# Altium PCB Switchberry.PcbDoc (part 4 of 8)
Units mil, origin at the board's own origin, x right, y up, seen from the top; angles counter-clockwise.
Board outline 4500 x 3824.8 mil, 6 copper layers (L01-TOP, L02-GND, L03-SIG, L04-SIG, L05-GND, L06-BOT), stack 49.214 mil thick; 431 components, 322 nets, 1699 pads, 1274 vias.
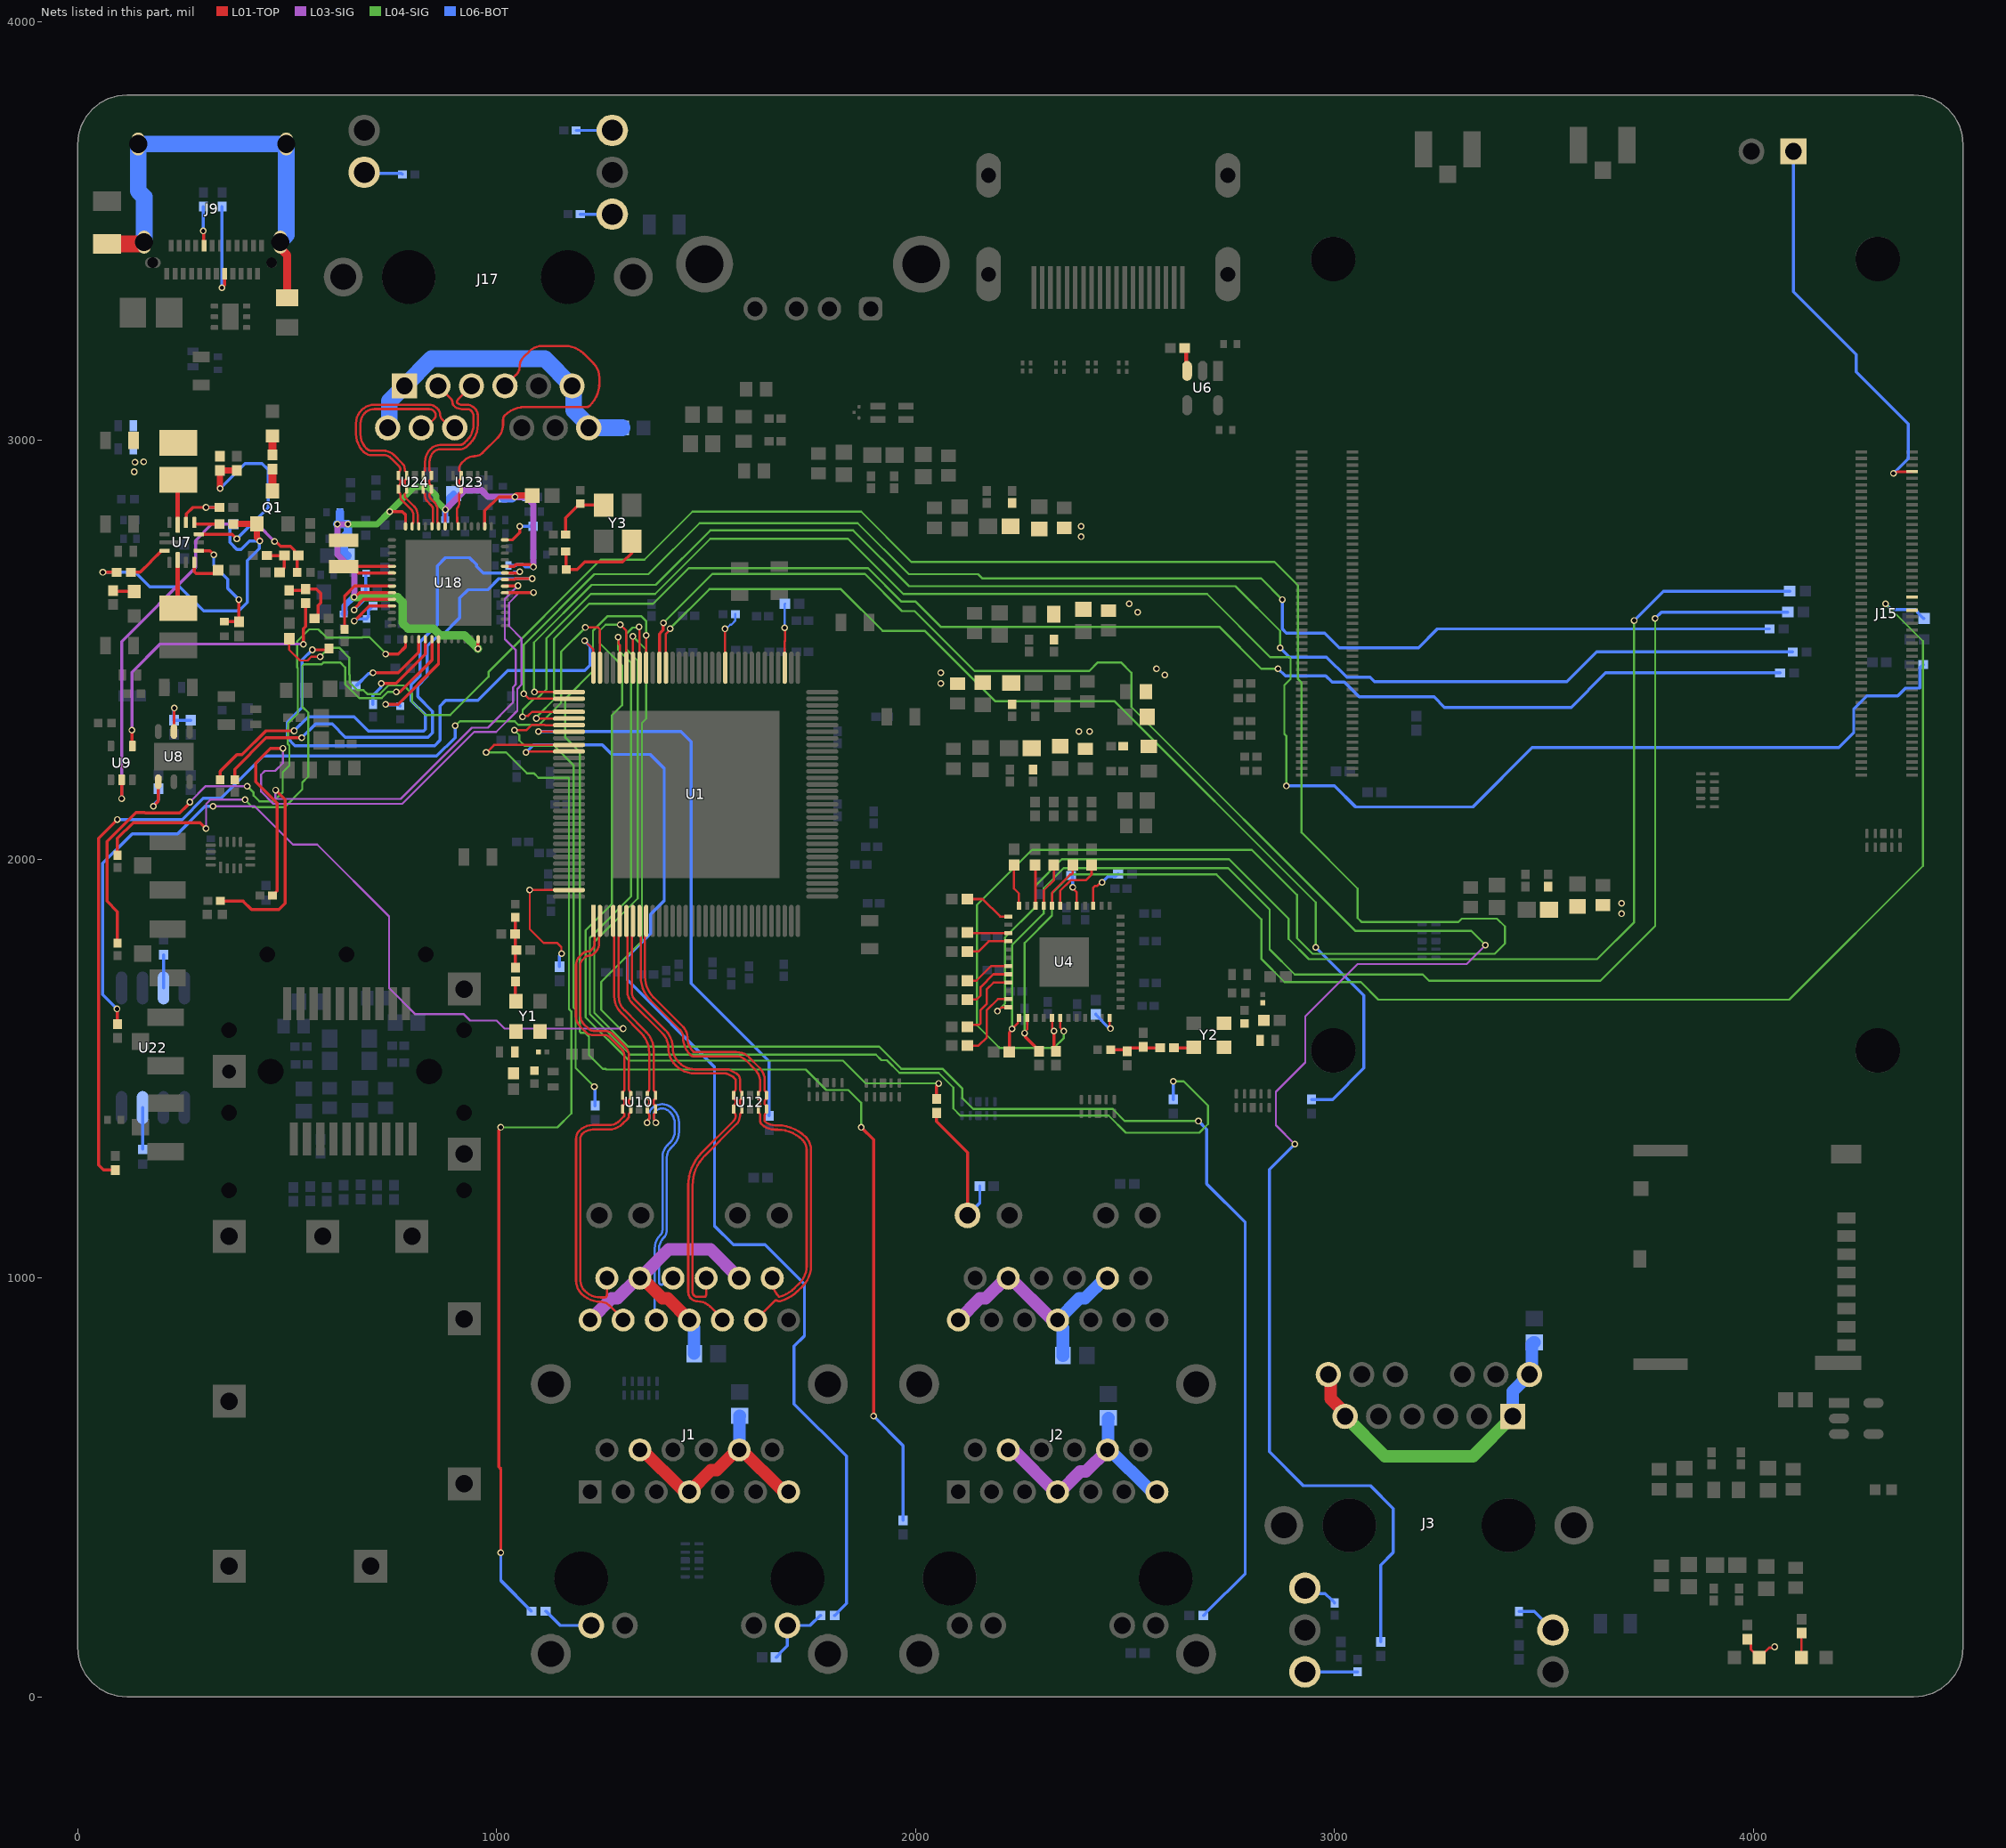
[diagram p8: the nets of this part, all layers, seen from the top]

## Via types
v1: diameter 16, hole 10, L01-TOP to L06-BOT, tented both sides, 1262 vias
v2: diameter 11.81, hole 7.87, L01-TOP to L06-BOT, tented both sides, 4 vias
v3: diameter 19.68, hole 7.87, L01-TOP to L06-BOT, tented both sides, 4 vias
v4: diameter 157.48, hole 110.24, L01-TOP to L06-BOT, tented both sides, 4 vias

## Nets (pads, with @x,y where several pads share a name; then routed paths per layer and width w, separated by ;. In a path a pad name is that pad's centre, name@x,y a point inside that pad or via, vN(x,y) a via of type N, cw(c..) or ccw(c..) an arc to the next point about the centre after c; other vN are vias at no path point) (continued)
MDI_B_P: J17.4 U18.48 U23.2 U23.9 | length 922.7
  L01-TOP w5.38: U18.48@908.62,2794.84 908.62,2799.53 ccw(c904.04,2799.53) 907.28,2802.77 cw(c910.52,2806.01) 905.94,2806.01 905.94,2816.09 ccw(c903.59,2816.09) 905.25,2817.75 905.25,2837.45 ccw(c892.18,2850.52) 910.66,2850.52 910.66,2868.5 cw(c919.05,2868.5) 913.12,2874.44 913.81,2875.13 914.07,2875.13 914.69,2875.75 ccw(c913.18,2877.26) 915.31,2877.26 U23.2@915.31,2883.56 915.31,2889.87 ccw(c913.18,2889.87) 914.69,2891.37 914.07,2892 913.81,2892 cw(c921.42,2899.6) 910.66,2899.6 910.66,2902.63 cw(c916.04,2902.63) 912.24,2906.43 913.81,2908 914.07,2908 ccw(c911.05,2911.02) 915.31,2911.02 915.31,2921.86 ccw(c911.05,2921.86) 914.07,2924.87 913.81,2924.87 912.24,2926.45 cw(c916.04,2930.25) 910.66,2930.25 910.66,2932.54 cw(c928.18,2932.54) 915.79,2944.93 923.43,2952.57 cw(c946.7,2929.31) 946.7,2962.21 ccw(c946.7,2990.59) 966.77,2970.52 1002.09,3005.85 ccw(c970.01,3037.92) 1015.38,3037.92 1015.38,3048.84 cw(c1031.16,3048.84) 1020,3060 cw(c1067.37,3012.63) 1067.37,3079.62 1215,3079.62 ccw(c1215,3090) 1222.34,3082.66 ccw(c1166.72,3138.28) 1245.38,3138.28 1245.38,3150 ccw(c1198.79,3150) 1231.73,3182.95 1207.34,3207.34 ccw(c1163.79,3163.79) 1163.79,3225.38 1109.14,3225.38 ccw(c1109.14,3180.86) 1077.66,3212.34 1065.06,3199.73 ccw(c1089.79,3175) 1054.81,3175 cw(c1030.21,3175) 1047.61,3157.61 J17.4@1020,3130
MDI_C_N: J17.2 U18.52 U24.4 U24.7 | length 481.8
  L01-TOP w5.38: U24.7@824.68,2911.02 U24.7@824.68,2916.44 ; U24.7@824.72,2909.47 824.72,2921.95 cw(c828.85,2921.95) 825.93,2924.87 826.19,2924.87 827.76,2926.45 ccw(c823.96,2930.25) 829.34,2930.25 829.34,2948.32 cw(c873.47,2948.32) 842.26,2979.52 cw(c865.08,2956.7) 865.08,2988.98 911,2988.98 ccw(c911,3006.42) 923.33,2994.09 929.61,3000.36 ccw(c893.05,3036.91) 944.75,3036.91 944.75,3058.54 ccw(c928.54,3058.54) 940,3070 ccw(c928.84,3058.84) 928.84,3074.62 917.26,3074.62 cw(c917.26,3102.07) 897.85,3082.66 cw(c905.19,3090) 894.81,3090 ccw(c882.28,3090) 891.14,3098.86 J17.2@860,3130 ; U24.7@825.93,2908 826.19,2908 827.76,2906.43 cw(c823.96,2902.63) 829.34,2902.63 829.34,2899.6 cw(c818.58,2899.6) 826.19,2892 825.93,2892 825.31,2891.37 ccw(c826.82,2889.87) 824.68,2889.87 U24.4@824.68,2883.56 824.68,2878.14 ccw(c828.95,2878.14) 825.93,2875.13 826.19,2875.13 827.76,2873.55 cw(c823.96,2869.75) 829.34,2869.75 829.34,2865.86 ccw(c844.1,2865.86) 833.66,2855.42 843.48,2845.6 cw(c831.81,2833.93) 848.32,2833.93 848.32,2806.01 cw(c843.73,2806.01) 846.97,2802.77 ccw(c850.21,2799.53) 845.63,2799.53 U18.52@845.63,2794.84
MDI_C_P: J17.3 U18.51 U24.5 U24.6 | length 478
  L01-TOP w5.38: U18.51@861.38,2794.84 861.38,2799.53 ccw(c856.79,2799.53) 860.04,2802.77 cw(c863.28,2806.01) 858.69,2806.01 858.69,2833.93 ccw(c831.81,2833.93) 850.82,2852.94 842.52,2861.24 cw(c849.29,2868.01) 839.72,2868.01 839.72,2869.75 cw(c845.09,2869.75) 841.29,2873.55 842.87,2875.13 843.12,2875.13 ccw(c840.11,2878.14) 844.37,2878.14 U24.5@844.37,2883.56 844.37,2889.87 ccw(c842.24,2889.87) 843.75,2891.37 843.12,2892 842.87,2892 cw(c850.47,2899.6) 839.72,2899.6 839.72,2902.63 cw(c845.09,2902.63) 841.29,2906.43 842.87,2908 843.12,2908 ccw(c840.11,2911.02) 844.37,2911.02 U24.6@844.37,2916.44 844.37,2921.86 ccw(c840.11,2921.86) 843.12,2924.87 842.87,2924.87 841.29,2926.45 cw(c845.09,2930.25) 839.72,2930.25 839.72,2948.32 cw(c873.47,2948.32) 849.6,2972.19 cw(c865.08,2956.7) 865.08,2978.6 911,2978.6 ccw(c911,3006.42) 930.67,2986.75 936.94,2993.02 ccw(c893.05,3036.91) 955.13,3036.91 955.13,3058.54 ccw(c928.54,3058.54) 947.34,3077.34 ccw(c928.84,3058.84) 928.84,3085 917.26,3085 cw(c917.26,3102.07) 905.19,3090 cw(c917.72,3090) 908.86,3098.86 J17.3@940,3130
MDI_D_N: J17.9 U18.55 U24.1 U24.10 | length 620.9
  L01-TOP w5.38: U18.55@798.39,2794.84 798.39,2799.53 cw(c802.97,2799.53) 799.73,2802.77 ccw(c796.49,2806.01) 801.07,2806.01 801.07,2822.76 ccw(c784.01,2822.76) 796.08,2834.82 774.3,2856.59 cw(c784.01,2866.29) 770.28,2866.29 770.28,2869.75 ccw(c764.91,2869.75) 768.71,2873.55 767.13,2875.13 766.88,2875.13 cw(c769.89,2878.14) 765.63,2878.14 U24.1@765.63,2883.56 765.63,2889.87 cw(c767.76,2889.87) 766.25,2891.37 766.88,2892 767.13,2892 ccw(c759.53,2899.6) 770.28,2899.6 770.28,2902.63 ccw(c764.91,2902.63) 768.71,2906.43 767.13,2908 766.88,2908 cw(c769.89,2911.02) 765.63,2911.02 U24.10@765.63,2916.44 765.63,2922.74 cw(c767.76,2922.74) 766.25,2924.25 766.88,2924.87 767.13,2924.87 767.83,2925.56 ccw(c761.89,2931.5) 770.28,2931.5 ccw(c761.96,2931.5) 767.85,2937.38 747.46,2957.77 ccw(c730,2940.31) 730,2965 701.16,2965 cw(c701.16,2991.16) 682.66,2972.66 681.8,2973.52 cw(c723.28,3015) 664.62,3015 664.62,3040.86 cw(c709.14,3040.86) 677.66,3072.34 cw(c708.69,3041.31) 708.69,3085.19 838.38,3085.19 cw(c838.38,3058.38) 857.34,3077.34 860.13,3074.55 cw(c847.9,3062.33) 865.19,3062.33 ccw(c882.48,3062.33) 870.25,3050.1 883.54,3036.82 ccw(c900,3053.28) J17.9@900,3030
MDI_D_P: J17.8 U18.54 U24.2 U24.9 | length 588.1
  L01-TOP w5.38: U18.54@814.13,2794.84 814.13,2799.53 ccw(c809.55,2799.53) 812.79,2802.77 cw(c816.03,2806.01) 811.45,2806.01 811.45,2822.76 ccw(c784.01,2822.76) 803.41,2842.16 783.16,2862.41 cw(c789.2,2868.44) 780.66,2868.44 780.66,2869.75 cw(c786.04,2869.75) 782.24,2873.55 783.81,2875.13 784.07,2875.13 ccw(c781.05,2878.14) 785.31,2878.14 U24.2@785.31,2883.56 785.31,2889.87 ccw(c783.18,2889.87) 784.69,2891.37 784.07,2892 783.81,2892 cw(c791.42,2899.6) 780.66,2899.6 780.66,2902.63 cw(c786.04,2902.63) 782.24,2906.43 783.81,2908 784.07,2908 ccw(c781.05,2911.02) 785.31,2911.02 U24.9@785.31,2916.44 785.31,2922.74 ccw(c783.18,2922.74) 784.69,2924.25 784.07,2924.87 783.81,2924.87 783.12,2925.56 cw(c789.05,2931.5) 780.66,2931.5 ccw(c761.96,2931.5) 775.18,2944.72 754.8,2965.11 ccw(c730,2940.31) 730,2975.38 701.16,2975.38 cw(c701.16,2991.16) 690,2980 689.14,2980.86 cw(c723.28,3015) 675,3015 675,3040.86 cw(c709.14,3040.86) 685,3065 cw(c708.69,3041.31) 708.69,3074.81 838.38,3074.81 cw(c838.38,3058.38) 850,3070 851.27,3068.73 cw(c842.71,3060.18) 854.81,3060.18 cw(c842.71,3060.18) 851.27,3051.62 836.46,3036.82 cw(c820,3053.28) J17.8@820,3030
NetC17_1: C17.1 C18.1 C19.1 L1.2 Y1.1 Y1.4
NetC23_1: C23.1 C24.1 C25.1 L2.2 Y2.1 Y2.4
NetC26_2: C26.2 J1.4 J1.7 J1.9 J1.12 | length 561.1
  L01-TOP w30: J1.9@1342,590 1347.95,590 1443.23,494.72 1455.28,494.72 J1.4@1460,490 1511.67,541.67 1525.02,541.67 1573.35,590 J1.12@1579,590 1584.95,590 1680.23,494.72 1692.28,494.72 J1.7@1697,490
  L06-BOT w30: J1.12@1579,590 1579.5,590.5 1579.5,670.96 C26.2@1580,671.46
NetC27_2: C27.2 J2.4 J2.7 J2.9 J2.12 | length 556.5
  L03-SIG w30: J2.9@2221,590 2225.72,585.28 2237.77,585.28 2333.05,490 J2.4@2339,490 2344.65,490 2392.98,538.33 2406.33,538.33 J2.12@2458,590
  L06-BOT w30: C27.2@2460,666.46 2459,665.46 2459,591 J2.12@2458,590 2463.95,590 2559.23,494.72 2571.28,494.72 J2.7@2576,490
NetC28_2: C28.2 J3.1 J3.6 J3.7 J3.12 | length 794.7
  L01-TOP w30: J3.12@2985,770 2990.79,764.21 2990.79,712.4 3025,678.18 J3.6@3025,670
  L04-SIG w30: J3.6@3025,670 3120,575 3330,575 J3.1@3425,670
  L06-BOT w30: J3.1@3425,670 3425,730 J3.7@3465,770 3465,778.18 3471.21,784.39 3471.21,843.1 3474.91,846.8 C28.2@3476.88,846.8
NetC29_2: C29.2 J2.14 J2.17 J2.22 J2.25 | length 570.4
  L03-SIG w30: J2.14@2102,900 2153.67,951.67 2167.02,951.67 2215.35,1000 J2.22@2221,1000 2226.95,1000 2322.23,904.72 2334.28,904.72 J2.17@2339,900
  L06-BOT w30: C29.2@2351.46,815 2351.46,880.86 2339,893.32 J2.17@2339,900 2390.67,951.67 2404.02,951.67 2452.35,1000 J2.25@2458,1000
NetC31_2: C31.2 J1.14 J1.17 J1.22 J1.25 | length 698.4
  L01-TOP w30: J1.22@1342,1000 1347.65,1000 1395.98,951.67 1408.33,951.67 J1.17@1460,900
  L03-SIG w30: J1.14@1223,900 1274.67,951.67 1288.02,951.67 1336.35,1000 J1.22@1342,1000 1410.56,1068.56 1510.44,1068.56 J1.25@1579,1000
  L06-BOT w30: J1.17@1460,900 1460,893.32 1471.46,881.86 C31.2@1471.46,820
NetC61_1: C61.1 J9.1 J9.2 J9.3 J9.4 R76.1 | length 1063.9
  L01-TOP w20: J9.1@483.86,3473.27 483.86,3458.35 500,3442.2 R76.1@500,3340.43
  L01-TOP w40: C61.1@70,3468.8 154.41,3468.8 158.66,3473.06 J9.2@158.66,3473.27
  L06-BOT w40: J9.2@158.66,3473.27 158.66,3581.18 144.49,3595.35 J9.4@144.49,3707.52 J9.3@498.03,3707.52 498.03,3490.75 483.86,3476.57 J9.1@483.86,3473.27
NetC62_1: C62.1 R80.1 U9.2 | length 1069.9
  L01-TOP w7.27: v1(105,2145) U9.2@105,2189.65 ; v1(470.18,2758.65) 472.55,2758.65 484.24,2746.96 508.13,2746.96 517.57,2737.51 517.57,2733.18 525.75,2725 R80.1@526.73,2725 524.25,2722.52 C62.1@524.25,2685
  L03-SIG w7.27: v1(105,2145) 105,2520 281.5,2696.5 281.5,2761.24 320.26,2800 428.84,2800 v1(470.18,2758.65)
NetC174_1: C174.1 R29.2 R104.1 R105.2 | length 120.3
  L01-TOP w7.27: C174.1@1044.92,1861.54 1044.92,1822.27 R105.2@1044.34,1821.69 1045,1821.03 R29.2@1045,1741.73
NetC175_1: C175.1 R30.2 R106.1 R107.2 | length 122.9
  L01-TOP w7.27: C175.1@2465.75,1545 2501.73,1545 R107.2@2505,1541.73 2505,1542.72 2512.28,1550 R30.2@2583.27,1550
NetC186_2: C186.2 R140.1 Y3.3 | length 243.9
  L01-TOP w7.27: R140.1@1164.76,2735 1165.54,2734.23 1165.54,2692.73 C186.2@1166.31,2691.95 1191.95,2691.95 1210,2710 1301.04,2710 1322.6,2731.56 Y3.3@1322.6,2759.12
NetC187_2: C187.2 R138.1 Y3.1 | length 143.5
  L01-TOP w7.27: R138.1@1164.76,2775 1164.76,2814.76 1195.73,2845.73 Y3.1@1255.67,2845.73
NetC189_2: C189.2 J17.1 J17.6 J17.7 J17.12 | length 766.4
  L06-BOT w40: J17.7@740,3030 743.87,3033.87 743.87,3093.87 J17.1@780,3130 845,3195 1115,3195 J17.6@1180,3130 1183.87,3126.13 1183.87,3071.6 1220,3035.48 J17.12@1220,3030 C189.2@1299.41,3030
NetD1_1: D1.1 R26.2 | length 58.4
  L01-TOP w6: D1.1@4114.25,94.37 4114.25,152.27 R26.2@4114.59,152.61
NetD2_1: D2.1 R27.2 | length 102.9
  L01-TOP w6: R27.2@3985,138.27 3993.81,129.46 3993.81,113.86 D2.1@4013.31,94.37 4037.03,118.09 4048.09,118.09 v1(4050,120)
NetD5_1: D5.1 R70.2 | length 45.5
  L01-TOP w20: R70.2@465,2965 D5.1@465,3010.47
NetD6_1: D6.1 R77.2 | length 50.9
  L01-TOP w7.27: R77.2@85,2641.73 87.2,2639.53 D6.1@135,2639.53
NetJ3_13: J3.13 R53.1 | length 99.4
  L06-BOT w7.27: R53.1@3440,204.53 3476.47,204.53 J3.13@3521,160
NetJ3_15: J3.15 R108.1 | length 86.2
  L06-BOT w7.27: J3.15@2929,260 2941.64,247.36 2977.4,247.36 2992.81,231.96 2993.79,231.96 3000,225.75 R108.1@3000,224.76
NetJ3_17: J3.17 R54.1 | length 126.1
  L06-BOT w7.27: J3.17@2929,60 2929.12,60.12 3054.88,60.12 R54.1@3055,60.24
NetJ9_A5: J9.A5 R65.1 | length 230.6
  L01-TOP w7.27: v1(344.62,3364.24) 350.79,3370.41 J9.A5@350.79,3398.07
  L06-BOT w7.27: v1(344.62,3364.24) 344.81,3364.43 344.81,3558.08 R65.1@345,3558.27
NetJ9_B5: J9.B5 R66.1 | length 93.9
  L01-TOP w7.27: v1(300,3500) 300.79,3499.21 300.79,3465.79 J9.B5@301.57,3465
  L06-BOT w7.27: v1(300,3500) R66.1@300,3558.27
NetJ15_51: J15.51
NetJ15_55: J15.55
NetJ17_13: J17.13 R146.1 | length 93.3
  L06-BOT w7.27: J17.13@684,3640 686.5,3637.5 772.74,3637.5 R146.1@775.24,3635
NetJ17_15: J17.15 R151.1 | length 76.2
  L06-BOT w7.27: R151.1@1199.76,3540 J17.15@1276,3540
NetJ17_17: J17.17 R150.1 | length 86.2
  L06-BOT w7.27: R150.1@1189.76,3740 J17.17@1276,3740
NetL8_1: L8.1 U7.6 | length 108
  L01-TOP w10: U7.6@238.79,2798.15 238.79,2904.47 L8.1@240,2905.68
NetL9_1: L9.1 U7.12 | length 115.7
  L01-TOP w10: U7.12@238.79,2714.49 238.79,2600.53 L9.1@240,2599.32
NetL10_1: L10.1 U18.5 U18.6 | length 200.5
  L01-TOP w7.27: L10.1@652.54,2699.37 U18.5@750.16,2699.37 ; L10.1@653.82,2699.37 669.57,2683.62 U18.6@750.16,2683.62
NetQ1_3: Q1.3 R70.1 | length 52.2
  L01-TOP w20: Q1.3@465,2879.37 R70.1@465,2931.54
NetR14_2: R14.2 U4.24 | length 102.3
  L01-TOP w5.38: R14.2@2235,1986.3 2235,1930 2246.73,1918.27 U4.24@2246.73,1888.86
NetR15_2: R15.2 U4.25 | length 114.7
  L01-TOP w5.38: R15.2@2123.7,1905 2160,1905 2201.73,1863.27 U4.25@2221.14,1863.27
NetR16_2: R16.2 U4.19 | length 149.7
  L01-TOP w5.38: U4.19@2345.16,1888.86 2345.16,1925.16 2370,1950 2406.34,1950 2420,1963.66 R16.2@2420,1986.3
NetR17_2: R17.2 U4.20 | length 119.8
  L01-TOP w5.38: U4.20@2325.47,1888.86 2325.47,1920.47 2368.66,1963.66 2371.85,1963.66 2375,1966.81 R17.2@2375,1986.3
NetR18_2: R18.2 U4.21 | length 107.5
  L01-TOP w5.38: U4.21@2305.79,1888.86 2305.79,1925.79 2330,1950 R18.2@2330,1986.3
NetR19_2: R19.2 U4.22 | length 97.9
  L01-TOP w5.38: R19.2@2285,1986.3 2286.1,1985.2 U4.22@2286.1,1888.86
NetR20_2: R20.2 U4.35 | length 181.7
  L01-TOP w5.38: R20.2@2123.7,1555 2150,1555 2170,1575 2170,1640 2196.42,1666.42 U4.35@2221.14,1666.42
NetR21_2: R21.2 U4.33 | length 180.4
  L01-TOP w5.38: R21.2@2123.7,1600 2128.7,1605 2151.85,1605 2155,1608.15 2155,1640 2170,1655 2170,1690 2185.79,1705.79 U4.33@2221.14,1705.79
NetR22_2: R22.2 U4.32 | length 134.2
  L01-TOP w5.38: R22.2@2123.7,1665 2145,1665 2155,1675 2155,1695 2185.47,1725.47 U4.32@2221.14,1725.47
NetR23_2: R23.2 U4.31 | length 112
  L01-TOP w5.38: R23.2@2123.7,1710 2145,1710 2180.16,1745.16 U4.31@2221.14,1745.16
NetR24_2: R24.2 U4.28 | length 107.5
  L01-TOP w5.38: R24.2@2123.7,1780 2150,1780 2174.21,1804.21 U4.28@2221.14,1804.21
NetR25_2: R25.2 U4.27 | length 97.9
  L01-TOP w5.38: R25.2@2123.7,1825 2124.8,1823.9 U4.27@2221.14,1823.9
NetR29_1: R29.1 Y1.3 | length 47.5
  L01-TOP w7.27: R29.1@1045,1708.27 1045,1662.87 Y1.3@1046.46,1661.42
NetR30_1: R30.1 Y2.3 | length 47.5
  L01-TOP w7.27: R30.1@2616.73,1550 2662.13,1550 Y2.3@2663.58,1551.46
NetR31_1: R31.1 U1.105 | length 2603.4
  L01-TOP w5.38: v1(975,2255) 975.71,2255 993.79,2273.08 U1.105@1172.79,2273.08
  L01-TOP w7.27: v1(1010,345) 1010,545 1005,550 1005,1352.64 1010,1357.64 v1(1010,1360)
  L04-SIG w4.97: v1(975,2255) 1022.63,2255 1072.14,2205.49 1088.55,2205.49 1099.67,2194.37 1172.71,2194.37 1172.71,1642.29 1178.61,1636.39 1178.61,1393.61 1145,1360 v1(1010,1360)
  L06-BOT w7.27: v1(1010,345) 1010,278.27 R31.1@1083.27,205
NetR32_1: R32.1 U1.106 | length 2816.3
  L01-TOP w5.38: v1(1070,2255) 1072.87,2255 1075.24,2257.36 U1.106@1172.82,2257.36
  L06-BOT w7.27: v1(1070,2255) 1088.08,2273.08 1252.37,2273.08 1275.2,2250.26 1366.71,2250.26 1400,2216.97 1400,1901.6 1367.27,1868.88 1367.27,1822.69 1312.33,1767.75 1312.33,1711.99 1520,1504.32 1520,1125 1565,1080 1640.49,1080 1734.76,985.72 1734.76,862.74 1710,837.98 1710,700 1835,575 1835,223.27 1814.91,203.18 1814.91,202.19 1807.72,195 R32.1@1806.73,195
NetR33_1: R33.1 U1.91 | length 2091.6
  L01-TOP w5.38: v1(1295,2560) 1309.49,2545.51 1309.49,2457.34 U1.91@1309.65,2457.18
  L01-TOP w7.27: R33.1@2050.16,1427.89 2050.16,1457.8 2055,1462.64 v1(2055,1465)
  L04-SIG w4.97: v1(1295,2560) 1260.25,2560 1246.57,2546.32 1246.57,2515.36 1299.26,2462.67 1299.26,2367.93 1275.2,2343.87 1275.2,1893.28 1212.15,1830.23 1212.15,1622.97 1315.86,1519.26 1826.71,1519.26 1880.96,1465 v1(2055,1465)
NetR34_1: R34.1 U1.92 | length 2852.7
  L01-TOP w5.38: v1(1290,2530) 1291.21,2528.79 1291.21,2513.93 1293.9,2511.24 U1.92@1293.9,2457.18
  L04-SIG w4.97: v1(1290,2530) 1290,2500.32 1320.94,2469.38 1320.94,1911.35 1222.46,1812.87 1222.46,1630.15 1318.83,1533.78 1905.32,1533.78 1918.61,1520.49 1931.28,1520.49 1961.74,1490.03 2054.97,1490.03 2090,1455 2090,1405 2106.76,1388.24 2460.95,1388.24 2501.85,1347.34 2677.34,1347.34 2697.94,1367.94 2697.94,1412.06 2640,1470 v1(2615,1470)
  L06-BOT w7.27: R34.1@2615,1426.73 v1(2615,1470)
NetR35_1: R35.1 U1.88 | length 3062.4
  L01-TOP w5.38: v1(1356.71,2534.59) 1356.8,2534.5 1356.8,2457.27 U1.88@1356.89,2457.18
  L01-TOP w7.27: v1(1870,1360) 1899.48,1330.52 v1(1899.48,670.78)
  L04-SIG w4.97: v1(1356.71,2534.59) 1356.71,2569.19 1345.9,2580 1264.13,2580 1230.14,2546 1230.14,2449.59 1163.89,2383.35 1163.89,2290.39 1198.56,2255.72 1198.56,1588.4 1201.47,1585.49 1211.41,1585.49 1220.49,1576.41 1220.49,1532.61 1253.59,1499.51 1260.19,1499.51 1261.57,1498.14 1737.71,1498.14 1786.58,1449.27 1839.38,1449.27 1870,1418.65 v1(1870,1360)
  L06-BOT w7.27: v1(1899.48,670.78) 1970,600.27 R35.1@1970,421.73
NetR36_1: R36.1 U1.89 | length 3925
  L01-TOP w5.38: v1(1340,2555) 1341.02,2553.98 1341.02,2457.3 U1.89@1341.14,2457.18
  L04-SIG w4.97: v1(1340,2555) 1338.09,2553.09 1324.54,2553.09 1309.49,2538.03 1309.49,2501.43 1336.97,2473.95 1336.97,1906.55 1233.31,1802.9 1233.31,1633.4 1313.79,1552.91 1912.95,1552.91 1965.87,1500 2063.76,1500 2111.57,1452.19 2111.57,1429.56 2137.24,1403.89 2470.31,1403.89 2499.19,1375 v1(2675,1375)
  L06-BOT w7.27: v1(2675,1375) 2695,1355 2695,1225 2786.63,1133.36 2786.63,294.9 2694.91,203.18 2694.91,202.19 2687.72,195 R36.1@2686.73,195
NetR37_1: R37.1 U1.85 | length 2586.5
  L01-TOP w5.38: U1.85@1404.13,2457.18 1404.13,2537.94 1414.01,2547.82 v1(1414.01,2550.69)
  L04-SIG w4.97: v1(1414.01,2550.69) 1414.01,2550.91 1507.79,2644.69 1821.78,2644.69 1920.98,2545.49 2021.76,2545.49 2190.25,2376.99 2475.14,2376.99 2955,1897.13 v1(2955,1790)
  L06-BOT w7.27: R37.1@2945,1426.73 2995.2,1426.73 3070,1501.53 3070,1675 v1(2955,1790)
NetR38_1: R38.1 U1.86 | length 4848.5
  L01-TOP w7.27: U1.86@1388.42,2457.21 1388.42,2538 1393.39,2542.98 1393.39,2543.21 1397.08,2546.9 1397.08,2563.37 v1(1398.03,2564.31)
  L03-SIG w4.97: v1(2904.8,1320) 2859.8,1365 2859.8,1444.8 2930,1515 2930,1625 3055,1750 3315,1750 v1(3360,1795)
  L04-SIG w4.97: v1(1398.03,2564.31) 1515.21,2681.5 1878.5,2681.5 1967.5,2592.5 1997.5,2592.5 2140.49,2449.51 2414.51,2449.51 2435,2470 2490,2470 2515,2445 2515,2363.58 3049.24,1829.34 3325.66,1829.34 v1(3360,1795)
  L06-BOT w7.27: v1(2904.8,1320) 2844.39,1259.59 2844.39,585.61 2925.36,504.64 3085.36,504.64 3140,450 3140,345.32 3110,315.32 R38.1@3110,131.73
NetR39_1: R39.1 U1.102 | length 1152.9
  L01-TOP w5.38: v1(1042.52,2308.08) 1070.96,2308.08 1083.56,2320.69 1115.19,2320.69 1115.53,2320.35 U1.102@1172.82,2320.35
  L04-SIG w4.97: v1(1042.52,2308.08) 1054.11,2296.49 1054.11,2283.99 1067.61,2270.49 1137.89,2270.49 1183.46,2224.91 1183.46,1646.54 1188.45,1641.55 1188.45,1640.65 1188.59,1640.52 1188.59,1501.58 v1(1233.2,1456.97)
  L06-BOT w7.27: v1(1233.2,1456.97) 1235,1455.17 R39.1@1235,1411.73
NetR40_1: R40.1 U1.103 | length 1417.6
  L01-TOP w5.38: v1(1100,2305) 1100.2,2304.8 1172.62,2304.8 U1.103@1172.82,2304.61
  L06-BOT w7.27: v1(1100,2305) 1440,2305 1464.44,2280.56 1464.44,1703.49 1650.47,1517.46 R40.1@1650.47,1387.52
NetR42_2: R42.2 U1.76 | length 141.4
  L01-TOP w5.38: v1(1545,2550) 1545.43,2549.57 1545.43,2457.62 U1.76@1545.87,2457.18
  L06-BOT w5.38: v1(1545,2550) 1547.72,2550 1557.72,2560 1560,2560 1569.76,2569.76 R42.2@1569.76,2585
NetR43_1: R43.1 U1.96 | length 1265.1
  L01-TOP w5.38: v1(1210,2521.78) 1230.91,2500.88 U1.96@1230.91,2457.18
  L01-TOP w7.27: v1(560,2500) 593.04,2500 R43.1@594.4,2501.36
  L06-BOT w7.27: v1(560,2500) 536.09,2476.09 536.09,2362.64 500.25,2326.8 500.25,2289.75 518.73,2271.27 852.01,2271.27 865,2284.26 865,2365.71 878.34,2379.05 955.35,2379.05 1026.5,2450.21 1210,2450.21 1223.3,2463.51 1223.3,2508.35 1210,2521.65 v1(1210,2521.78)
NetR44_1: R44.1 U1.100 | length 4379.7
  L01-TOP w5.38: v1(1062.05,2340.11) 1064.92,2340.11 1067.22,2342.41 1075.29,2342.41 1084.94,2352.07 1112.75,2352.07 1112.97,2351.85 U1.100@1172.82,2351.85
  L04-SIG w4.97: v1(1062.05,2340.11) 1062.05,2356.7 1088.59,2383.24 1096.01,2383.24 1118.76,2406 1118.76,2527.37 1224.64,2633.25 1378.25,2633.25 1510,2765 1838.96,2765 1970.71,2633.25 2695.58,2633.25 2846.2,2482.63 2892.09,2482.63 2895,2479.72 2895,2430.37 2880,2415.37 2880,2299.18 2885,2294.18 v1(2885,2175)
  L06-BOT w7.27: v1(2885,2175) 3000,2175 3050,2125 3330,2125 3471.6,2266.6 4203.23,2266.6 4238.92,2302.29 4238.92,2358.4 4270.52,2390 4344.13,2390 4362.71,2408.58 4396.84,2408.58 4396.84,2457.51 4404.03,2464.7 R44.1@4405.02,2464.7
NetR45_2: R45.2 U1.101 | length 3453.1
  L01-TOP w5.38: v1(1095,2336.38) 1095.14,2336.24 1172.68,2336.24 U1.101@1172.82,2336.1
  L04-SIG w4.97: v1(1095,2336.38) 1095,2339.36 1099.4,2343.77 1099.4,2343.89 1137.11,2381.6 1137.11,2526.38 1220.74,2610 1373.34,2610 1458.34,2695 1886.56,2695 1966.56,2615 2000,2615 2060,2555 2725,2555 2825,2455 v1(2865,2455)
  L06-BOT w7.27: v1(2865,2455) 2882.36,2437.63 2978.84,2437.63 2993.84,2422.63 3023.54,2422.63 3058.54,2387.63 3237.18,2387.63 3262.07,2362.74 3564.52,2362.74 3646.78,2445 R45.2@4063.27,2445
NetR46_2: R46.2 U1.98 | length 3506
  L01-TOP w5.38: v1(1065,2395) 1076.55,2383.45 1112.81,2383.45 1112.91,2383.35 U1.98@1172.82,2383.35
  L04-SIG w4.97: v1@1064.71,2395.29 1064.71,2511.99 1233.2,2680.49 1362.37,2680.49 1484.31,2802.42 1861.7,2802.42 1983.63,2680.49 2148.89,2680.49 2158.55,2670.83 2824.17,2670.83 v1(2875,2620)
  L06-BOT w7.27: v1(2875,2620) 2875,2550 2885,2540 2976.47,2540 3011.47,2505 3200,2505 3245,2550 R46.2@4038.27,2550
NetR47_2: R47.2 U1.97 | length 3519.3
  L01-TOP w5.38: v1@1090.02,2399.11 U1.97@1172.8,2399.11
  L04-SIG w4.97: v1(1090,2399.13) 1089.01,2400.13 1089.01,2517.45 1226.56,2655 1380,2655 1510,2785 1851.19,2785 1984.17,2652.02 2762.98,2652.02 2870,2545 v1(2870,2505)
  L06-BOT w7.27: v1(2870,2505) 2892.36,2482.63 2980.89,2482.63 3029.16,2434.37 3084.16,2434.37 3094.82,2423.7 3554.31,2423.7 3625.61,2495 R47.2@4093.27,2495
NetR48_2: R48.2 U1.95 | length 2418.3
  L01-TOP w5.38: v1(1211.72,2553.28) 1241.72,2553.28 1246.65,2548.35 U1.95@1246.65,2457.18
  L01-TOP w7.27: R48.2@90,1258.27 61.73,1258.27 50,1270 50,2050 v1(95,2095)
  L04-SIG w4.97: v1(900.93,2319.07) 902.3,2319.07 912.55,2329.31 1043.19,2329.31 1051.61,2320.89 1101.41,2320.89 1153.92,2373.4 1153.92,2495.48 v1(1211.72,2553.28)
  L06-BOT w7.27: v1(95,2095) 249.69,2095 300.16,2145.47 341.95,2145.47 443.11,2246.63 856.96,2246.63 900.93,2290.61 v1(900.93,2319.07)
NetR49_1: R49.1 U1.90 | length 3111.5
  L01-TOP w5.38: U1.90@1325.39,2457.18 v1(1325.33,2531.98)
  L01-TOP w7.27: v1(93.97,1642.72) 94.49,1642.21 94.49,1607.25 R49.1@95,1606.73
  L03-SIG w4.97: v1(323.36,2126.63) 422.25,2126.63 513.71,2035.17 571.73,2035.17 743.23,1863.67 743.23,1693.15 806.37,1630 921.62,1630 936.62,1615 1000,1615 1019.15,1595.85 v1(1302.11,1595.85)
  L04-SIG w4.97: v1(1302.11,1595.85) 1300.14,1597.83 1292.17,1597.83 1249.51,1640.49 1249.51,1707.31 1346.94,1804.74 1346.94,2325.39 1356.85,2335.3 1356.85,2500.47 v1(1325.33,2531.98)
  L06-BOT w7.27: v1(93.97,1642.72) 60,1676.69 60,1990.59 130.35,2060.95 238.67,2060.95 304.35,2126.63 v1(323.36,2126.63)
NetR50_1: R50.1 U1.67 | length 153.7
  L01-TOP w5.38: v1(1687.23,2552.87) 1687.98,2552.12 1687.98,2520.57 1687.6,2520.18 U1.67@1687.6,2457.18
  L06-BOT w5.38: v1(1687.23,2552.87) 1687.23,2608.97 R50.1@1688.27,2610
NetR51_1: R51.1 U1.127 | length 329.7
  L01-TOP w4.97: v1(1078.96,1926.57) 1078.96,1833.45 1112.41,1800 1145,1800 1154.54,1790.46 1154.54,1775.46 v1(1155,1775)
  L01-TOP w5.38: v1(1078.96,1926.57) v1(1078.96,1926.57) 1172.77,1926.61 U1.127@1172.82,1926.65
  L06-BOT w7.27: R51.1@1150,1743.46 1150,1770 v1(1155,1775)
NetR55_2: R55.2 U6.3 | length 56.5
  L01-TOP w10: R55.2@2641.73,3220 2645.49,3216.24 2645.49,3168.59 U6.3@2648.01,3166.07
NetR58_1: R58.1 R59.2 U7.3 | length 520.3
  L01-TOP w7.27: U7.3@289.47,2776 369,2776 v1(380,2765)
  L01-TOP w15: v1(340,2885) R58.1@340,2928.27 R59.2@380,2928.27
  L06-BOT w7.27: v1(340,2885) 400,2945 440,2945 454.74,2930.26 454.74,2839.74 v1(380,2765)
NetR60_2: R60.2 R61.2 U7.1 | length 260
  L01-TOP w7.27: U7.1@289.47,2736.63 315.35,2736.63 v1(324.83,2727.16) ; R61.2@350,2567.72 384.02,2567.72 R60.2@385,2566.73 v1(385,2620)
  L06-BOT w7.27: v1(324.83,2727.16) 324.83,2701.66 358.36,2668.13 358.36,2646.63 v1(385,2620)
NetR62_1: R62.1 R67.2 U7.5 | length 137.7
  L01-TOP w7.27: U7.5@258.47,2804.06 259.76,2805.34 259.76,2824.76 275,2840 v1(306.63,2840) R62.1@338.27,2840
  L06-BOT w7.27: v1(306.63,2840) R67.2@338.27,2840
NetR63_1: R63.1 U7.4 | length 63.4
  L01-TOP w7.27: U7.4@278.16,2804.06 278.16,2801.29 279.44,2800 R63.1@338.27,2800
NetR64_2: R64.2 U7.10 | length 102.8
  L01-TOP w7.27: R64.2@126.73,2685 149.45,2685 174.28,2709.83 174.28,2710.51 200.4,2736.63 U7.10@207.78,2736.63
NetR68_2: R68.2 U7.14 | length 83.9
  L01-TOP w7.27: U7.14@278.16,2708.58 278.23,2708.5 278.23,2686.77 282.64,2682.36 327.68,2682.36 R68.2@335.31,2690
NetR69_1: R69.1 U8.1 | length 109.4
  L01-TOP w7.27: v1(180.71,2126.8) 192.6,2138.69 U8.1@192.6,2184.96
  L06-BOT w7.27: v1(180.71,2126.8) 180.71,2129.17 192.6,2141.05 R69.1@192.6,2168.23
NetR72_1: R72.1 R73.2 U8.5 | length 125.6
  L01-TOP w7.27: U8.5@230,2305.04 230.26,2305.3 230.26,2360.74 v1(230.51,2361)
  L06-BOT w7.27: v1(230.51,2361) 230,2360.49 R73.2@230,2331.73 R72.1@270,2331.73
NetR75_2: R75.2 R78.1 R81.2 | length 147
  L01-TOP w7.27: R81.2@505,2641.73 540.93,2641.73 R78.1@544.21,2645.01 569.99,2645.01 580,2635 580,2611.82 573.64,2605.46 573.64,2582.29 566.45,2575.09 R75.2@565.47,2575.09
NetR78_2: R78.2 U9.4 | length 714.9
  L01-TOP w7.27: v1(129.4,2307.96) 129.99,2307.36 129.99,2270.95 U9.4@130.59,2270.35 ; v1(539.14,2513.18) 539.14,2550.86 544.21,2555.92 R78.2@544.21,2611.55
  L03-SIG w7.27: v1(129.4,2307.96) 129.4,2446.37 196.78,2513.76 538.56,2513.76 v1(539.14,2513.18)
NetR79_1: R79.1 R80.2 R82.1 | length 86.9
  L01-TOP w7.27: R79.1@451.73,2725 R80.2@493.27,2725 493.27,2695.55 482.72,2685 R82.1@481.73,2685
NetR83_1: R83.1 U4.42 | length 6192.8
  L01-TOP w4.97: R83.1@505,2526.3 505,2500 530.59,2474.41 548.75,2474.41 557.7,2483.37 v1(578.86,2483.37)
  L01-TOP w5.38: U4.42@2345.16,1621.14 2345.16,1598.36 v1(2353.87,1589.65)
  L04-SIG w4.97: v1(578.86,2483.37) 599.95,2504.46 625.14,2504.46 648.39,2481.2 648.39,2440.61 648.99,2440.01 648.99,2421.76 666.96,2403.79 682.05,2403.79 691.32,2394.51 721.41,2394.51 741.87,2414.97 778.25,2414.97 798.18,2395.04 798.18,2376.34 830,2344.51 889.23,2344.51 980.49,2435.77 980.49,2447.11 1248.37,2715 1352.57,2715 1467.57,2830 1870,2830 1990,2710 2856.4,2710 2912.72,2653.68 2912.72,2429.88 2921.3,2421.3 2921.3,2063.7 3055,1930 3055,1860 3065,1850 3295,1850 3303.41,1858.41 3387.55,1858.41 3406.34,1839.62 3406.34,1798.66 3382,1774.32 2947.7,1774.32 2910,1812.02 2910,1915 2802.6,2022.4 2277.72,2022.4 2146.34,1891.02 2146.34,1603.66 2198.34,1551.66 2200.38,1549.62 2330,1549.62 2353.87,1573.49 v1(2353.87,1589.65)
NetR84_2: R84.2 U4.36 | length 3106.2
  L01-TOP w5.38: v1(2195.4,1637.33) 2204.8,1646.73 U4.36@2221.14,1646.73
  L04-SIG w4.97: v1(2195.4,1637.33) 2213.42,1655.35 2213.42,1813.42 2286.1,1886.1 2286.1,1937.03 2349.45,2000.38 2747.95,2000.38 2890,1858.33 2890,1810 2938.44,1761.56 3626.56,1761.56 3715,1850 v1(3715,2570)
  L06-BOT w7.27: v1(3715,2570) 3785,2640 R84.2@4086.3,2640
NetR85_1: R85.1 R87.1 U4.38 | length 3636
  L01-TOP w5.38: v1(2260,1585) 2260,1587.87 2266.42,1594.29 U4.38@2266.42,1621.14
  L01-TOP w7.27: v1(2260,1585) 2261.67,1583.33 2261.67,1576.05 2295,1542.72 R85.1@2295,1541.73
  L04-SIG w4.97: v1(2260,1585) 2260,1800 2325.47,1865.47 2325.47,1918.69 2370.44,1963.66 2717.91,1963.66 2825,1856.58 2825,1762.48 2880.72,1706.76 3062.58,1706.76 3104.34,1665 4085,1665 4404.27,1984.27 4404.27,2520.73 v1(4315,2610)
  L06-BOT w7.27: v1(4315,2610) 4328.63,2596.37 4386.41,2596.37 4391.47,2591.31 4391.47,2588.94 4405.47,2574.94 R87.1@4406.46,2574.94
NetR86_2: R86.2 R88.2 U4.37 | length 3215.3
  L01-TOP w5.38: v1(2230,1595) 2244.5,1609.5 2244.5,1618.91 U4.37@2246.73,1621.14
  L01-TOP w7.27: R88.2@2223.7,1540 2223.7,1586.34 2230,1592.64 v1(2230,1595)
  L04-SIG w4.97: v1(2230,1595) 2230,1795 2305.79,1870.79 2305.79,1931.23 2353.35,1978.79 2746.21,1978.79 2845,1880 2845,1784.87 2904.87,1725 3210.39,1725 3225.39,1710 3634.34,1710 3765,1840.66 v1(3765,2575)
  L06-BOT w7.27: v1(3765,2575) 3780,2590 R86.2@4081.3,2590
NetR89_2: R89.2 U4.48 | length 76
  L01-TOP w5.38: U4.48@2463.27,1621.14 2463.27,1598.15 v1(2465.39,1596.03)
  L06-BOT w7.27: R89.2@2430,1630 2430,1629.02 2461.32,1597.7 2463.72,1597.7 v1(2465.39,1596.03)
NetR90_1: R90.1 U4.41 | length 83.4
  L01-TOP w5.38: U4.41@2325.47,1621.14 2325.47,1594.53 v1(2330,1590)
  L01-TOP w7.27: v1(2330,1590) 2330,1546.73 R90.1@2335,1541.73
NetR95_1: R95.1 U4.17 | length 77.8
  L01-TOP w5.38: v1(2375.19,1933) 2375.19,1930.12 2384.53,1920.78 U4.17@2384.53,1888.86
  L06-BOT w7.27: R95.1@2371.43,1961.19 2375.19,1957.43 v1(2375.19,1933)
NetR96_1: R96.1 U4.15 | length 116.3
  L01-TOP w5.38: U4.15@2423.9,1888.86 2424.01,1888.97 2424.01,1932.35 2427.81,1936.15 2433.19,1936.15 2442.08,1945.04 v1(2444.96,1945.04)
  L06-BOT w7.27: v1(2444.96,1945.04) 2445.23,1945.04 2458.46,1958.28 2476.54,1958.28 R96.1@2483.27,1965
NetR109_1: R109.1 R113.2 U18.10 | length 202.5
  L01-TOP w7.27: v1(660,2595) 660,2597.36 671.95,2609.31 671.95,2610.48 682.1,2620.63 U18.10@750.16,2620.63
  L06-BOT w7.27: v1(660,2595) 680.98,2615.98 680.98,2634.35 687.27,2640.63 687.27,2681.22 R109.1@688.81,2682.76
NetR110_1: R110.1 R112.2 U18.11 | length 173.7
  L01-TOP w7.27: v1(660.44,2568.97) 696.36,2604.88 U18.11@750.16,2604.88
  L06-BOT w7.27: v1(660.44,2568.97) 662.81,2568.97 667.95,2574.11 R110.1@689.53,2574.11 694.25,2578.83 694.25,2593.87 698.06,2597.69 698.06,2598.67 704.27,2604.88 R112.2@705.26,2604.88
NetR121_2: R121.2 U18.15 | length 1458.4
  L01-TOP w7.27: R121.2@95,1799.76 95,1875 70,1900 70,2042.35 139.17,2111.52 160,2111.52 161.35,2110.17 243.69,2110.17 261.63,2128.11 267.77,2134.25 v1(267.77,2136.61) ; v1(735,2490) 765.2,2490 782.64,2507.44 U18.15@782.64,2525.16
  L03-SIG w4.97: v1(267.77,2136.61) 305.78,2174.62 v1(404.49,2174.62)
  L04-SIG w4.97: v1(404.49,2174.62) 420.16,2158.95 420.16,2152.07 433.72,2138.51 467.79,2138.51 489.51,2160.24 489.51,2207.84 505.49,2223.81 505.49,2271.41 501.4,2275.5 501.4,2313.05 502.31,2313.96 502.31,2324.46 525.49,2347.63 525.49,2456.41 523.66,2458.24 523.66,2519.59 552.79,2548.72 574.68,2548.72 593.92,2529.48 678.8,2529.48 679.8,2530.49 696.41,2530.49 735,2491.9 v1(735,2490)
NetR122_1: R122.1 U18.8 | length 202.3
  L01-TOP w7.27: R122.1@637.18,2548.75 637.18,2628.11 661.2,2652.13 U18.8@750.16,2652.13
NetR124_1: R124.1 U18.34 | length 1689
  L01-TOP w7.27: R124.1@464.76,1913.38 465.75,1913.38 471.96,1919.59 471.96,1920.58 475.84,1924.46 475.84,2134.16 425,2185 425,2230 460,2265 v1(490,2265) ; U18.34@1019.84,2636.38 1057.85,2636.38 1058.11,2636.63 1066.63,2636.63 1066.97,2636.97 v1(1088.15,2636.97)
  L03-SIG w4.97: v1(490,2265) 490,2229.48 471.36,2210.84 446.82,2210.84 437.89,2201.92 437.89,2161.9 467.44,2132.35 774.92,2132.35 946.57,2304 999,2304 1049.31,2354.31 1049.31,2406.74 1059.59,2417.02 1059.59,2526.83 1029.51,2556.9 1029.51,2612.18 1054.3,2636.97 v1(1088.15,2636.97)
NetR125_1: R125.1 U18.35 | length 1472.4
  L01-TOP w7.27: R125.1@340.38,1900.67 394.33,1900.67 ; 395,1900 394.33,1900.67 ; v1(472.61,2165.23) 495,2142.84 495,1894.5 480.5,1880 415,1880 394.33,1900.67 ; U18.35@1019.84,2652.13 1019.96,2652.24 1050.2,2652.24 v1(1050.97,2653.01)
  L03-SIG w4.97: v1(472.61,2165.23) 471.79,2164.42 471.79,2147.01 474.71,2144.1 771,2144.1 940.87,2313.97 978.97,2313.97 1039.34,2374.34 1039.34,2410.87 1045.43,2416.96 1045.43,2420.43 ; 1045.43,2417.25 1045.43,2420.43 ; v1(1050.97,2653.01) 1019.54,2621.59 1019.54,2525.69 1045.43,2499.8 1045.43,2420.43
NetR126_1: R126.1 U18.36 | length 1201.2
  L01-TOP w7.27: R126.1@375,2189.76 375,2215 450,2290 v1(535,2290) ; U18.36@1019.84,2667.87 1042.3,2667.87 1044.43,2670 v1(1085,2670)
  L06-BOT w7.27: v1(535,2290) 568.02,2323.02 607.76,2323.02 639.14,2291.63 836.63,2291.63 847.01,2302.01 847.01,2352.99 811.54,2388.46 811.54,2413.98 834.51,2436.95 834.51,2508.83 860.49,2534.81 869.95,2534.81 911.67,2576.53 911.67,2623.58 931.45,2643.36 978.5,2643.36 1005.14,2670 v1(1085,2670)
NetR129_1: R129.1 U18.37 | length 1269.6
  L01-TOP w7.27: R129.1@340,2189.76 340,2210 380,2250 392.65,2250 449.28,2306.63 v1(516.88,2306.63) ; U18.37@1019.84,2683.62 1049.62,2683.62 1052.64,2686.63 v1(1055,2686.63)
  L06-BOT w7.27: v1(516.88,2306.63) 550.18,2339.93 660.07,2339.93 693.82,2306.18 825.74,2306.18 830,2310.44 830,2345 796.25,2378.75 796.25,2416.9 817.5,2438.14 817.5,2519.16 858.78,2560.45 858.78,2700.62 878.17,2720 935.14,2720 951.82,2703.32 951.82,2699.57 968.45,2682.95 1039.54,2682.95 1041.56,2684.96 1053.33,2684.96 v1(1055,2686.63)
NetR131_2: R131.2 U18.17 | length 213.2
  L01-TOP w7.27: v1(705,2445) 765,2445 814.13,2494.13 U18.17@814.13,2525.16
  L06-BOT w7.27: R131.2@664.76,2415 665.75,2415 694.08,2443.33 703.33,2443.33 v1(705,2445)
NetR132_2: R132.2 U18.18 | length 227.6
  L01-TOP w7.27: v1(725,2420) 760,2420 829.88,2489.88 U18.18@829.88,2525.16
  L06-BOT w7.27: R132.2@705,2369.76 705,2391.47 723.33,2409.8 723.33,2418.33 v1(725,2420)
NetR133_2: R133.2 U18.19 | length 1356
  L01-TOP w7.27: R133.2@95,2009.76 95,2050 132.61,2087.61 292.39,2087.61 v1(306.59,2073.41) ; v1(760.49,2399.48) 769.48,2399.48 845.63,2475.63 U18.19@845.63,2525.16
  L03-SIG w4.97: v1(306.59,2073.41) 306.59,2131.76 316.95,2142.12 v1(399.6,2142.12)
  L04-SIG w4.97: v1(399.6,2142.12) 417.54,2124.18 493.59,2124.18 536.21,2166.8 536.21,2183.62 550.49,2197.89 550.49,2349.9 536.09,2364.29 536.09,2461.09 540.49,2465.49 582.88,2465.49 587.39,2470 626.39,2470 638.42,2457.96 638.42,2418.22 672.1,2384.54 725.54,2384.54 740.48,2399.48 v1(760.49,2399.48)
NetR134_2: R134.2 U18.42 | length 89.7
  L01-TOP w7.27: U18.42@1019.84,2762.36 1037.36,2762.36 1055,2780 v1(1055,2795)
  L06-BOT w7.27: v1(1055,2795) R134.2@1087.28,2795
NetR135_2: R135.2 U18.20 | length 261.8
  L01-TOP w7.27: v1(735,2370) 765,2370 861.38,2466.38 U18.20@861.38,2525.16
  L06-BOT w7.27: v1(735,2370) 736.67,2368.33 767.5,2368.33 R135.2@770,2365.83
NetR136_1: R136.1 U22.3 | length 79.5
  L06-BOT w7.27: U22.3@205,1692.72 R136.1@205,1772.2
NetR137_1: R137.1 U22.7 | length 99.5
  L06-BOT w7.27: R137.1@155,1307.8 U22.7@155,1407.28
nRPIBOOT: J15.93 J18.1 | length 942.4
  L01-TOP w6: v1(4333.71,2921) cw(c4344.16,2910.55) 4344.16,2925.33 J15.93@4377.9,2925.33
  L06-BOT w7.27: J18.1@4095,3690 4095,3355 4245,3205 4245,3163.4 4368.89,3039.5 4368.89,2956.18 v1(4333.71,2921)
P0V95_I225: C191.2 C193.2 C195.2 C197.2 C199.2 C201.2 C203.2 C205.2 C207.1 C209.1 C211.1 L10.2 U18.9 U18.26 U18.38 U18.44 U18.50 U18.56 | length 2162.1
  L01-TOP w7.27: v1(660,2626.08) 662.36,2626.08 672.66,2636.38 U18.9@750.16,2636.38 ; v1(745,2830) 775,2830 782.64,2822.36 U18.56@782.64,2794.84 ; U18.50@877.13,2794.84 877.24,2794.96 877.24,2833.96 v1(877.87,2834.58) ; v1(955.48,2502.67) 955.48,2518.7 955.87,2519.09 U18.26@955.87,2525.16 ; U18.44@971.61,2794.84 971.61,2831.61 1005.16,2865.16 v1(1043.94,2865.16) ; U18.38@1019.84,2699.37 1041.95,2699.37 1045.85,2703.27 1079.96,2703.27 1085.4,2697.84 v1(1087.76,2697.84)
  L01-TOP w15: v1(1043.94,2865.16) 1044.21,2865.16 1047.36,2868.31 C207.1@1084.98,2868.31
  L03-SIG w15: v1(645,2800) v1(620,2800) 620,2727.61 660.53,2687.08 660.53,2629.41 660.19,2629.07 660.19,2626.27 v1(660,2626.08) ; v1(877.87,2834.58) 924.24,2880.96 963.82,2880.96 979.62,2865.16 v1(1043.94,2865.16) 1044.13,2864.97 1070.05,2864.97 1087.76,2847.26 v1(1087.76,2697.84)
  L04-SIG w15: v1(645,2800) 715,2800 v1(745,2830) 803.86,2888.86 835.27,2888.86 856.46,2867.67 856.46,2856.26 877.87,2834.85 v1(877.87,2834.58)
  L04-SIG w20: v1(660,2626.08) 763.67,2626.08 775.39,2614.36 775.39,2563.86 788.86,2550.39 849.61,2550.39 865.03,2534.97 923.18,2534.97 v1(955.48,2502.67)
  L06-BOT w7.27: C203.2@1028.09,2701.42 1046.26,2701.42 1048.11,2703.27 1062.91,2703.27 1068.34,2697.84 v1(1087.76,2697.84) 1087.66,2697.94 1087.66,2727.46 C193.2@1087.56,2727.56
  L06-BOT w15: C201.2@635,2585.75 636.97,2585.75 637.34,2586.12 637.34,2604.86 658.37,2625.89 659.81,2625.89 v1(660,2626.08) ; C195.2@877.18,2810.65 877.18,2833.63 877.87,2834.31 v1(877.87,2834.58) 877.87,2834.85 887.29,2844.28 887.29,2862.87 C211.1@897.61,2873.19 ; C191.2@1015,2859.25 1015.37,2859.63 1038.14,2859.63 1043.67,2865.16 v1(1043.94,2865.16) 1044.02,2865.08 1069.17,2865.08 C205.2@1069.25,2865
  L06-BOT w20: v1(620,2800) 632.5,2800 ; C199.2@625.57,2828.31 625.57,2806.93 632.5,2800 ; C209.1@643.92,2724.51 636.1,2732.32 636.1,2759.65 C197.2@630.75,2765 645,2779.25 v1(645,2800) 632.5,2800
P1_LED0: J1.27 R31.2 | length 123.4
  L06-BOT w7.27: R31.2@1116.73,205 1117.72,205 1151.72,171 J1.27@1226,171
P1_LED1: J1.30 R32.2 R97.1 | length 177.1
  L06-BOT w7.27: R97.1@1666.73,95 1667.72,95 1675.89,103.18 1675.89,104.16 1694,122.27 J1.30@1694,171 1748.28,171 1772.28,195 R32.2@1773.27,195
P1_TXRXA_N: J1.21 U1.2 U10.2 U10.9 | length 1171.3
  L01-TOP w5.38: 1220,1770 ccw(c1220,1757.93) 1211.46,1766.46 1205,1760 ccw(c1217.07,1747.93) 1200,1747.93 1200,1625 ccw(c1224.14,1625) 1207.07,1607.93 1220,1595 ccw(c1231.16,1606.16) 1231.16,1590.38 1260.06,1590.38 cw(c1260.06,1568.08) 1275.83,1583.85 1305.55,1554.13 cw(c1281.12,1529.71) 1315.66,1529.71 1315.66,1452.48 ccw(c1326.42,1452.48) 1318.81,1444.87 1319.07,1444.87 1319.69,1444.25 cw(c1318.18,1442.74) 1320.31,1442.74 U10.9@1320.31,1436.44 1320.31,1431.02 cw(c1316.05,1431.02) 1319.07,1428 1318.81,1428 1317.24,1426.43 ccw(c1321.04,1422.63) 1315.66,1422.63 1315.66,1419.6 ccw(c1326.42,1419.6) 1318.81,1412 1319.07,1412 1319.69,1411.37 cw(c1318.18,1409.87) 1320.31,1409.87 U10.2@1320.31,1403.56 1320.31,1398.14 cw(c1316.05,1398.14) 1319.07,1395.13 1318.81,1395.13 1317.24,1393.55 ccw(c1321.04,1389.75) 1315.66,1389.75 1315.66,1387.6 cw(c1305.09,1387.6) 1312.58,1380.14 1301.48,1369.05 cw(c1267.57,1402.96) 1267.57,1355 1229.14,1355 ccw(c1229.14,1320.86) 1205,1345 ccw(c1217.07,1332.93) 1200,1332.93 1200,994.14 ccw(c1234.14,994.14) 1210,970 ccw(c1248.5,1008.5) 1248.5,954.05 1257.62,954.05 ccw(c1257.62,959.43) 1261.42,955.63 ccw(c1257.62,959.43) 1263,959.43 J1.21@1263,1000 ; 1220.04,1770 ccw(c1220.04,1787.52) 1232.43,1775.13 1236.03,1778.73 ccw(c1216.29,1798.48) 1244.21,1798.48 1244.21,1812.26 cw(c1246.63,1812.26) 1244.92,1813.98 ccw(c1243.21,1815.69) 1245.63,1815.69 1245.63,1850.34 cw(c1249.12,1850.34) U1.2@1246.65,1852.82
P1_TXRXA_P: J1.15 U1.1 U10.1 U10.10 | length 1200.5
  L01-TOP w5.38: U1.1@1230.91,1852.82 cw(c1224.45,1846.36) 1233.58,1846.36 1233.58,1813.77 1233.83,1813.52 1233.83,1798.54 cw(c1216.13,1798.54) 1228.65,1786.02 1225.12,1782.5 cw(c1220,1787.62) 1220,1780.38 1219.94,1780.38 ccw(c1219.94,1758.08) 1204.18,1773.85 1197.64,1767.32 ccw(c1217.01,1747.96) 1189.62,1747.96 1189.62,1624.94 ccw(c1224,1624.94) 1199.69,1600.63 1212.66,1587.66 ccw(c1231.16,1606.16) 1231.16,1580 1260,1580 cw(c1260,1567.93) 1268.54,1576.46 1298.16,1546.84 cw(c1280.96,1529.64) 1305.28,1529.64 1305.28,1452.48 cw(c1294.53,1452.48) 1302.13,1444.87 1301.88,1444.87 1301.25,1444.25 ccw(c1302.76,1442.74) 1300.63,1442.74 U10.10@1300.63,1436.44 1300.63,1431.02 ccw(c1304.89,1431.02) 1301.88,1428 1302.13,1428 1303.71,1426.43 cw(c1299.91,1422.63) 1305.28,1422.63 1305.28,1419.6 cw(c1294.53,1419.6) 1302.13,1412 1301.88,1412 1301.25,1411.37 ccw(c1302.76,1409.87) 1300.63,1409.87 U10.1@1300.63,1403.56 1300.63,1398.14 ccw(c1304.89,1398.14) 1301.88,1395.13 1302.13,1395.13 1303.71,1393.55 cw(c1299.91,1389.75) 1305.28,1389.75 cw(c1299.91,1389.75) 1303.71,1385.95 1294.21,1376.45 cw(c1267.48,1403.18) 1267.48,1365.38 1229.11,1365.38 ccw(c1229.11,1320.92) 1197.68,1352.36 ; J1.15@1302,900 ccw(c1298.32,900) 1300.92,902.6 1267.88,935.65 ccw(c1248.5,916.27) 1248.5,943.68 cw(c1248.5,1008.5) 1202.66,962.66 cw(c1234.14,994.14) 1189.62,994.14 1189.62,1332.96 cw(c1217.01,1332.96) 1197.64,1352.32 ; 1197.64,1352.32 1197.68,1352.36
P1_TXRXB_N: J1.16 U1.5 U10.5 U10.6 | length 1103.9
  L01-TOP w5.38: U1.5@1293.9,1852.82 1293.9,1820.14 cw(c1289.31,1820.14) 1292.56,1816.9 ccw(c1295.8,1813.66) 1291.21,1813.66 1291.21,1673.29 ccw(c1338.29,1673.29) 1305,1640 1334.84,1610.16 1334.84,1609.84 1357.38,1587.3 cw(c1315.51,1545.44) 1374.72,1545.44 1374.72,1452.48 ccw(c1385.47,1452.48) 1377.87,1444.87 1378.12,1444.87 1378.75,1444.25 cw(c1377.24,1442.74) 1379.37,1442.74 U10.6@1379.37,1436.44 1379.37,1431.02 cw(c1375.11,1431.02) 1378.12,1428 1377.87,1428 1376.29,1426.43 ccw(c1380.09,1422.63) 1374.72,1422.63 1374.72,1419.6 ccw(c1385.47,1419.6) 1377.87,1412 1378.12,1412 1378.75,1411.37 cw(c1377.24,1409.87) 1379.37,1409.87 U10.5@1379.37,1403.56 1379.37,1397.26 cw(c1377.24,1397.26) 1378.75,1395.75 1378.12,1395.13 1377.87,1395.13 ccw(c1385.47,1387.52) 1374.72,1387.52 1374.72,1383.05 ccw(c1383.78,1383.05) 1377.37,1376.63 v1@1378,1376.01 ; v1@1378,1376 cw(c1373.09,1371.1) v1(1380.03,1371.1)
  L06-BOT w5.38: v1@1378,1376 cw(c1373.09,1371.1) v1(1380.03,1371.1) ; v1@1378,1376.01 1377.37,1376.63 cw(c1383.78,1383.05) 1374.72,1383.05 1374.72,1391.17 cw(c1383.33,1391.17) 1377.24,1397.26 1377.89,1397.91 cw(c1395,1380.81) 1395,1405 cw(c1395,1380.86) 1412.07,1397.93 1415,1395 cw(c1390.86,1370.86) 1425,1370.86 1425,1350 cw(c1388.01,1350) 1414.16,1323.84 1407.6,1317.28 ccw(c1436.06,1288.81) 1395.81,1288.81 1395.81,1114.98 cw(c1379.71,1114.98) 1391.1,1103.59 ccw(c1424.07,1070.62) 1377.44,1070.62 1377.44,908.6 ccw(c1389.6,908.6) J1.16@1381,900
P1_TXRXB_P: J1.23 U1.4 U10.4 U10.7 | length 1086.1
  L01-TOP w5.38: U1.4@1278.15,1852.82 1278.15,1820.14 ccw(c1282.73,1820.14) 1279.49,1816.9 cw(c1276.25,1813.66) 1280.83,1813.66 1280.83,1673.2 ccw(c1338.08,1673.2) 1297.6,1632.72 1324.46,1605.86 1324.46,1605.54 1344.4,1585.6 ; v1(1359.03,1371.1) cw(c1365.97,1371.1) v1@1361.05,1376 ; v1@1361.06,1376.01 1361.68,1376.63 ccw(c1355.27,1383.05) 1364.34,1383.05 1364.34,1387.52 ccw(c1353.58,1387.52) 1361.19,1395.13 1360.93,1395.13 1360.31,1395.75 cw(c1361.82,1397.26) 1359.68,1397.26 U10.4@1359.68,1403.56 1359.68,1409.87 cw(c1361.82,1409.87) 1360.31,1411.37 1360.93,1412 1361.19,1412 ccw(c1353.58,1419.6) 1364.34,1419.6 1364.34,1422.63 ccw(c1358.96,1422.63) 1362.76,1426.43 1361.19,1428 1360.93,1428 cw(c1363.95,1431.02) 1359.68,1431.02 U10.7@1359.68,1436.44 1359.68,1442.74 cw(c1361.82,1442.74) 1360.31,1444.25 1360.93,1444.87 1361.19,1444.87 ccw(c1353.58,1452.48) 1364.34,1452.48 1364.34,1537.46 ccw(c1296.26,1537.46) 1344.44,1585.56 ; 1344.44,1585.56 ccw(c1296.26,1537.46) 1344.4,1585.6
  L06-BOT w5.38: v1(1359.03,1371.1) cw(c1365.97,1371.1) v1@1361.05,1376 ; v1@1361.06,1376.01 1361.68,1376.63 ccw(c1355.27,1383.05) 1364.34,1383.05 1364.34,1391.18 cw(c1383.3,1391.18) 1369.89,1404.59 1370.61,1405.31 cw(c1394.92,1381) 1394.92,1415.38 1395.1,1415.38 cw(c1395.1,1381.09) 1419.34,1405.34 1422.42,1402.25 cw(c1391.15,1370.98) 1435.38,1370.98 1435.38,1349.95 cw(c1388.12,1349.95) 1421.54,1316.54 1415,1310 ccw(c1436.27,1288.73) 1406.19,1288.73 1406.19,1114.98 cw(c1379.71,1114.98) 1398.43,1096.25 ccw(c1424.07,1070.62) 1387.81,1070.62 1387.81,989.97 ccw(c1393.19,989.97) 1389.39,986.17 ccw(c1393.19,989.97) 1393.19,984.59 ccw(c1393.19,989.97) 1396.99,986.17 1403.63,992.81 cw(c1421,975.44) J1.23@1421,1000
P1_TXRXC_N: J1.24 U1.7 U12.2 U12.9 | length 1176.9
  L01-TOP w5.38: U1.7@1325.39,1852.82 1325.39,1820.14 cw(c1320.81,1820.14) 1324.05,1816.9 ccw(c1327.29,1813.66) 1322.71,1813.66 1322.71,1682.94 ccw(c1348.41,1682.94) 1330.24,1664.76 1402.99,1592.01 cw(c1361.02,1550.03) 1420.38,1550.03 ; 1420.38,1550 ccw(c1469.57,1550) 1434.79,1515.21 ccw(c1473.75,1554.17) 1473.75,1499.08 1546.39,1499.08 cw(c1546.39,1475.15) 1552.99,1498.15 cw(c1546.39,1475.15) 1557.6,1496.29 1572.2,1488.59 cw(c1564.91,1474.62) 1576.05,1485.76 cw(c1564.91,1474.62) 1580.66,1474.68 1580.66,1474.62 1580.66,1452.48 ccw(c1591.42,1452.48) 1583.81,1444.87 1584.07,1444.87 1584.69,1444.25 cw(c1583.18,1442.74) 1585.31,1442.74 U12.9@1585.31,1436.44 1585.31,1431.02 cw(c1581.05,1431.02) 1584.07,1428 1583.81,1428 1582.24,1426.43 ccw(c1586.04,1422.63) 1580.66,1422.63 1580.66,1419.6 ccw(c1591.42,1419.6) 1583.81,1412 1584.07,1412 1584.69,1411.37 cw(c1583.18,1409.87) 1585.31,1409.87 U12.2@1585.31,1403.56 1585.31,1397.26 cw(c1583.18,1397.26) 1584.69,1395.75 1584.07,1395.13 1583.81,1395.13 ccw(c1591.42,1387.52) 1580.66,1387.52 ; J1.24@1500,1000 1500,960.55 cw(c1494.62,960.55) 1498.42,956.75 cw(c1494.62,960.55) 1494.62,955.18 1479.91,955.18 cw(c1479.91,967.88) 1470.93,958.9 cw(c1478.54,966.5) 1467.78,966.5 1467.78,1221.68 cw(c1567.78,1221.68) 1497.07,1292.39 1572.53,1367.86 ccw(c1552.92,1387.48) 1580.66,1387.48
P1_TXRXC_P: J1.18 U1.6 U12.1 U12.10 | length 1207.1
  L01-TOP w5.38: U1.6@1309.65,1852.82 1309.65,1820.14 ccw(c1314.23,1820.14) 1310.99,1816.9 cw(c1307.75,1813.66) 1312.33,1813.66 1312.33,1682.84 ccw(c1348.19,1682.84) 1322.83,1657.49 1395.63,1584.69 cw(c1360.94,1550) 1410,1550 ccw(c1469.51,1549.97) 1427.43,1507.89 1427.66,1507.66 ccw(c1473.45,1553.45) 1473.45,1488.7 1546.39,1488.7 cw(c1546.39,1475.15) 1552.84,1487.07 ; J1.18@1539,900 ccw(c1532.61,900) 1537.13,904.52 1509.11,932.54 ccw(c1479.51,902.94) 1479.51,944.8 cw(c1479.51,966.9) 1463.88,951.27 1463.59,951.56 cw(c1478.54,966.5) 1457.4,966.5 1457.4,966.9 1457.4,1221.73 cw(c1567.67,1221.73) 1489.7,1299.7 1565.16,1375.16 ccw(c1552.8,1387.52) 1570.28,1387.52 ccw(c1559.53,1387.52) 1567.13,1395.13 1566.88,1395.13 1566.25,1395.75 cw(c1567.76,1397.26) 1565.63,1397.26 U12.1@1565.63,1403.56 1565.63,1409.87 cw(c1567.76,1409.87) 1566.25,1411.37 1566.88,1412 1567.13,1412 ccw(c1559.53,1419.6) 1570.28,1419.6 1570.28,1422.63 ccw(c1564.91,1422.63) 1568.71,1426.43 1567.13,1428 1566.88,1428 cw(c1569.89,1431.02) 1565.63,1431.02 U12.10@1565.63,1436.44 1565.63,1442.74 cw(c1567.76,1442.74) 1566.25,1444.25 1566.88,1444.87 1567.13,1444.87 ccw(c1559.53,1452.48) 1570.28,1452.48 1570.28,1474.62 1564.91,1480 1563.99,1480.91 ccw(c1560.19,1477.11) 1562.7,1481.86 1552.84,1487.06
P1_TXRXD_N: J1.19 U1.9 U12.5 U12.6 | length 1280
  L01-TOP w5.38: U1.9@1356.89,1852.82 1356.89,1820.14 cw(c1352.31,1820.14) 1355.55,1816.9 ccw(c1358.79,1813.66) 1354.2,1813.66 1354.2,1720.2 ccw(c1425.2,1720.2) 1375,1670 1445.11,1599.89 cw(c1420.34,1575.11) 1455.38,1575.11 1455.38,1575 ccw(c1504.57,1575) 1469.79,1540.21 1470,1540 1571.81,1540 cw(c1571.81,1496.86) 1602.31,1527.36 1627.94,1501.74 cw(c1599.49,1473.3) 1627.98,1501.69 cw(c1599.49,1473.3) 1639.72,1473.3 1639.72,1450.25 ccw(c1645.09,1450.25) 1641.29,1446.45 1642.87,1444.87 1643.12,1444.87 cw(c1640.11,1441.86) 1644.37,1441.86 U12.6@1644.37,1436.44 1644.37,1430.13 cw(c1642.24,1430.13) 1643.75,1428.63 1643.12,1428 1642.87,1428 ccw(c1650.47,1420.4) 1639.72,1420.4 1639.72,1417.37 ccw(c1645.09,1417.37) 1641.29,1413.57 1642.87,1412 1643.12,1412 cw(c1640.11,1408.98) 1644.37,1408.98 U12.5@1644.37,1403.56 1644.37,1397.26 cw(c1642.24,1397.26) 1643.75,1395.75 1643.12,1395.13 1642.87,1395.13 ccw(c1650.47,1387.52) 1639.72,1387.52 1639.72,1375 ccw(c1663.86,1399.14) 1663.86,1365 1670.59,1365 cw(c1670.59,1270.65) 1737.31,1337.36 1737.37,1337.31 cw(c1705.97,1305.9) 1750.38,1305.9 1750.38,1029.16 cw(c1682.16,1029.16) 1730.4,980.92 1719,969.53 cw(c1653.84,1034.69) 1676.72,945.42 cw(c1674.2,955.49) 1669.48,946.25 ccw(c1667.05,941.45) 1668.07,946.73 1665.27,947.27 J1.19@1618,900
P1_TXRXD_P: J1.26 U1.8 U12.4 U12.7 | length 1235.7
  L01-TOP w5.38: U1.8@1341.14,1852.82 1341.14,1820.14 ccw(c1345.73,1820.14) 1342.48,1816.9 cw(c1339.24,1813.66) 1343.83,1813.66 1343.83,1720.16 ccw(c1425.09,1720.16) 1367.63,1662.69 1437.7,1592.62 cw(c1420.08,1575) 1445,1575 ccw(c1504.51,1574.97) 1462.43,1532.89 1462.67,1532.65 ccw(c1469.99,1539.97) 1469.99,1529.62 1571.77,1529.62 cw(c1571.77,1496.77) 1595,1520 1616.03,1498.97 cw(c1583.9,1466.84) 1629.34,1466.84 1629.34,1450.25 cw(c1623.96,1450.25) 1627.76,1446.45 1626.19,1444.87 1625.93,1444.87 ccw(c1628.95,1441.86) 1624.68,1441.86 U12.7@1624.68,1436.44 1624.68,1430.13 ccw(c1626.82,1430.13) 1625.31,1428.63 1625.93,1428 1626.19,1428 cw(c1618.58,1420.4) 1629.34,1420.4 1629.34,1417.37 cw(c1623.96,1417.37) 1627.76,1413.57 1626.19,1412 1625.93,1412 ccw(c1628.95,1408.98) 1624.68,1408.98 U12.4@1624.68,1403.56 1624.68,1397.26 ccw(c1626.82,1397.26) 1625.31,1395.75 1625.93,1395.13 1626.19,1395.13 cw(c1618.58,1387.52) 1629.34,1387.52 1629.34,1374.92 ccw(c1639.53,1374.92) 1632.32,1367.72 1632.44,1367.6 ccw(c1663.77,1398.94) 1663.77,1354.62 1670.56,1354.62 cw(c1670.56,1270.56) 1730,1330 cw(c1705.86,1305.86) 1740,1305.86 1740,1029.16 cw(c1682.16,1029.16) 1723.06,988.26 1711.66,976.87 cw(c1653.84,1034.69) 1674.2,955.49 cw(c1713.31,994.6) 1658,994.6 J1.26@1658,1000
P1V2: C48.1 C49.1 C51.2 C63.1 C64.2 C65.1 C78.1 C79.2 C80.1 C90.1 C91.2 C92.1 C119.1 C120.2 C121.1 C134.1 C135.2 C136.1 C157.1 C158.2 C159.1 FB5.1 FB6.1 FB9.1 FB11.1 L8.2 R58.2 R92.1 R93.1
  other v1: 3685,1870 3685,1895 2390,2305 2415,2305 2060,2420 2595,2440 2060,2445 2575,2455 2530,2590 2510,2610 2395,2770 2395,2795 135,2925 136.87,2948.12 157.85,2949.03
P1V2_PGOOD: Q1.1 R57.1 R63.2 R64.1 | length 816.9
  L01-TOP w7.27: v1(60.17,2685.08) 60.25,2685 R64.1@93.27,2685
  L01-TOP w15: R63.2@371.73,2800 372.05,2800.31 427.28,2800.31 Q1.1@427.6,2800.63 427.6,2767.67 435,2760.27 v1(435,2760)
  L06-BOT w7.27: v1(60.17,2685.08) 137.58,2685.08 171.91,2650.75 243.03,2650.75 300.42,2593.37 385,2593.37 405,2613.37 405,2712.99 433.33,2741.32 433.33,2758.33 v1(435,2760) 410,2760 390,2740 380,2740 363.36,2756.63 363.36,2791.82 371.54,2800 R57.1@371.73,2800
P2_LED0: J2.31 R33.2 R100.1 | length 357.1
  L01-TOP w7.27: R33.2@2050.16,1394.42 2050.16,1373.84 2124,1300 J2.31@2124,1150
  L06-BOT w7.27: J2.31@2124,1150 2124,1150.48 2153.27,1179.75 R100.1@2153.27,1220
